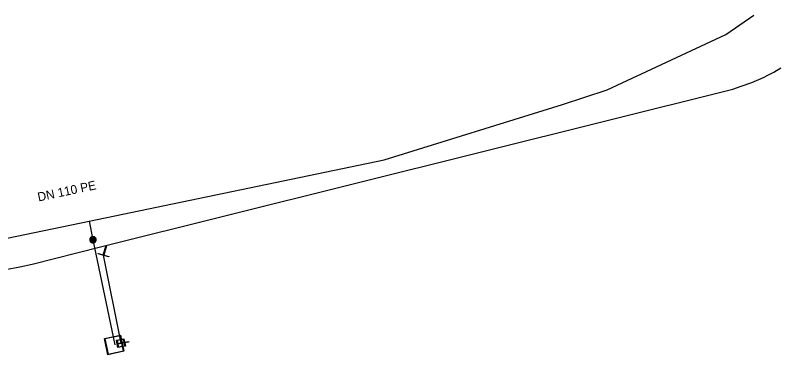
# Model space of a CAD drawing. Extents: x -818065 to -817466, y -1067968 to -1067520.
# Drawn here: x -817526.5 to -817466.3, y -1067819.3 to -1067792.5 of the extents above; entities that cross this region are included whole.
import ezdxf

# ---------------------------------------------------------------- set-up
doc = ezdxf.new("R2010")
doc.units = 0
doc.layers.add('Default', color=7, linetype='Continuous')
doc.layers.add('Level 0', color=7, linetype='Continuous')

msp = doc.modelspace()

# ---------------------------------------------------------------- linework, layer by layer
at = {"layer": 'Default'}
for points in [[(-817519.34, -1067810.682), (-817519.548, -1067811.408), (-817519.14, -1067811.525), (-817519.148, -1067811.554), (-817519.992, -1067811.312), (-817519.984, -1067811.282), (-817519.578, -1067811.4), (-817519.366, -1067810.663), (-817519.346, -1067810.658), (-817519.34, -1067810.682)], [(-817517.952, -1067818.98), (-817519.223, -1067819.251), (-817519.494, -1067817.979), (-817518.222, -1067817.709), (-817517.952, -1067818.98)], [(-817518.253, -1067817.757), (-817519.446, -1067818.01), (-817519.192, -1067819.202), (-817518, -1067818.949), (-817518.253, -1067817.757)], [(-817517.899, -1067818.263), (-817517.605, -1067818.205), (-817517.596, -1067818.254), (-817517.89, -1067818.311), (-817517.838, -1067818.581), (-817518.427, -1067818.696), (-817518.541, -1067818.107), (-817517.952, -1067817.992), (-817517.899, -1067818.263)], [(-817517.948, -1067818.272), (-817517.991, -1067818.05), (-817518.483, -1067818.146), (-817518.44, -1067818.368), (-817517.948, -1067818.272)], [(-817517.938, -1067818.32), (-817518.431, -1067818.416), (-817518.388, -1067818.638), (-817517.895, -1067818.542), (-817517.938, -1067818.32)]]:
    msp.add_lwpolyline(points, dxfattribs=at)
for points in [[(-817520.395, -1067809.954), (-817520.332, -1067809.954), (-817520.272, -1067809.986), (-817520.212, -1067810.018), (-817520.179, -1067810.079), (-817520.145, -1067810.139), (-817520.145, -1067810.204), (-817520.145, -1067810.269), (-817520.178, -1067810.329), (-817520.211, -1067810.388), (-817520.27, -1067810.421), (-817520.33, -1067810.454), (-817520.395, -1067810.454), (-817520.46, -1067810.454), (-817520.519, -1067810.421), (-817520.579, -1067810.388), (-817520.612, -1067810.329), (-817520.645, -1067810.269), (-817520.645, -1067810.204), (-817520.645, -1067810.139), (-817520.611, -1067810.079), (-817520.578, -1067810.018), (-817520.518, -1067809.986), (-817520.458, -1067809.954), (-817520.395, -1067809.954)], [(-817520.395, -1067809.977), (-817520.452, -1067809.977), (-817520.506, -1067810.007), (-817520.561, -1067810.036), (-817520.591, -1067810.09), (-817520.621, -1067810.145), (-817520.621, -1067810.204), (-817520.621, -1067810.263), (-817520.592, -1067810.317), (-817520.562, -1067810.371), (-817520.508, -1067810.401), (-817520.454, -1067810.431), (-817520.395, -1067810.431), (-817520.336, -1067810.431), (-817520.282, -1067810.401), (-817520.228, -1067810.371), (-817520.198, -1067810.317), (-817520.168, -1067810.263), (-817520.168, -1067810.204), (-817520.168, -1067810.145), (-817520.199, -1067810.09), (-817520.23, -1067810.036), (-817520.284, -1067810.007), (-817520.338, -1067809.977), (-817520.395, -1067809.977)], [(-817520.395, -1067809.995), (-817520.342, -1067809.995), (-817520.292, -1067810.022), (-817520.242, -1067810.049), (-817520.214, -1067810.099), (-817520.185, -1067810.149), (-817520.185, -1067810.204), (-817520.185, -1067810.259), (-817520.213, -1067810.309), (-817520.24, -1067810.358), (-817520.29, -1067810.386), (-817520.34, -1067810.414), (-817520.395, -1067810.414), (-817520.449, -1067810.414), (-817520.499, -1067810.386), (-817520.549, -1067810.358), (-817520.577, -1067810.309), (-817520.604, -1067810.259), (-817520.604, -1067810.204), (-817520.604, -1067810.149), (-817520.576, -1067810.099), (-817520.548, -1067810.049), (-817520.498, -1067810.022), (-817520.448, -1067809.995), (-817520.395, -1067809.995)], [(-817520.395, -1067810.017), (-817520.473, -1067810.017), (-817520.528, -1067810.071), (-817520.582, -1067810.126), (-817520.582, -1067810.204), (-817520.582, -1067810.282), (-817520.527, -1067810.337), (-817520.472, -1067810.392), (-817520.395, -1067810.392), (-817520.317, -1067810.392), (-817520.262, -1067810.337), (-817520.207, -1067810.282), (-817520.207, -1067810.204), (-817520.207, -1067810.126), (-817520.262, -1067810.071), (-817520.316, -1067810.017), (-817520.395, -1067810.017)], [(-817520.395, -1067810.039), (-817520.327, -1067810.039), (-817520.279, -1067810.087), (-817520.231, -1067810.135), (-817520.231, -1067810.204), (-817520.231, -1067810.272), (-817520.279, -1067810.32), (-817520.327, -1067810.368), (-817520.395, -1067810.368), (-817520.464, -1067810.368), (-817520.511, -1067810.32), (-817520.559, -1067810.272), (-817520.559, -1067810.204), (-817520.559, -1067810.135), (-817520.511, -1067810.087), (-817520.464, -1067810.039), (-817520.395, -1067810.039)], [(-817520.395, -1067810.059), (-817520.455, -1067810.059), (-817520.497, -1067810.102), (-817520.54, -1067810.144), (-817520.54, -1067810.204), (-817520.54, -1067810.263), (-817520.497, -1067810.306), (-817520.455, -1067810.348), (-817520.395, -1067810.348), (-817520.335, -1067810.348), (-817520.293, -1067810.306), (-817520.251, -1067810.263), (-817520.251, -1067810.204), (-817520.251, -1067810.144), (-817520.293, -1067810.102), (-817520.335, -1067810.059), (-817520.395, -1067810.059)], [(-817520.395, -1067810.079), (-817520.343, -1067810.079), (-817520.306, -1067810.116), (-817520.27, -1067810.152), (-817520.27, -1067810.204), (-817520.27, -1067810.256), (-817520.306, -1067810.293), (-817520.343, -1067810.329), (-817520.395, -1067810.329), (-817520.447, -1067810.329), (-817520.483, -1067810.293), (-817520.52, -1067810.256), (-817520.52, -1067810.204), (-817520.52, -1067810.152), (-817520.483, -1067810.116), (-817520.447, -1067810.079), (-817520.395, -1067810.079)], [(-817520.395, -1067810.102), (-817520.437, -1067810.102), (-817520.467, -1067810.132), (-817520.497, -1067810.162), (-817520.497, -1067810.204), (-817520.497, -1067810.246), (-817520.467, -1067810.276), (-817520.437, -1067810.305), (-817520.395, -1067810.305), (-817520.353, -1067810.305), (-817520.323, -1067810.276), (-817520.293, -1067810.246), (-817520.293, -1067810.204), (-817520.293, -1067810.162), (-817520.323, -1067810.132), (-817520.353, -1067810.102), (-817520.395, -1067810.102)], [(-817520.395, -1067810.12), (-817520.36, -1067810.12), (-817520.335, -1067810.144), (-817520.311, -1067810.169), (-817520.311, -1067810.204), (-817520.311, -1067810.239), (-817520.335, -1067810.263), (-817520.36, -1067810.288), (-817520.395, -1067810.288), (-817520.43, -1067810.288), (-817520.455, -1067810.263), (-817520.479, -1067810.239), (-817520.479, -1067810.204), (-817520.479, -1067810.169), (-817520.455, -1067810.144), (-817520.43, -1067810.12), (-817520.395, -1067810.12)], [(-817520.395, -1067810.142), (-817520.421, -1067810.142), (-817520.439, -1067810.16), (-817520.457, -1067810.178), (-817520.457, -1067810.204), (-817520.457, -1067810.23), (-817520.439, -1067810.248), (-817520.421, -1067810.267), (-817520.395, -1067810.267), (-817520.369, -1067810.267), (-817520.351, -1067810.248), (-817520.332, -1067810.23), (-817520.332, -1067810.204), (-817520.332, -1067810.178), (-817520.35, -1067810.16), (-817520.369, -1067810.142), (-817520.395, -1067810.142)], [(-817520.395, -1067810.165), (-817520.378, -1067810.165), (-817520.367, -1067810.176), (-817520.356, -1067810.187), (-817520.356, -1067810.204), (-817520.356, -1067810.22), (-817520.367, -1067810.232), (-817520.378, -1067810.243), (-817520.395, -1067810.243), (-817520.411, -1067810.243), (-817520.423, -1067810.232), (-817520.434, -1067810.22), (-817520.434, -1067810.204), (-817520.434, -1067810.187), (-817520.423, -1067810.176), (-817520.411, -1067810.165), (-817520.395, -1067810.165)], [(-817520.395, -1067810.181), (-817520.405, -1067810.181), (-817520.412, -1067810.187), (-817520.418, -1067810.194), (-817520.418, -1067810.204), (-817520.418, -1067810.214), (-817520.412, -1067810.221), (-817520.405, -1067810.227), (-817520.395, -1067810.227), (-817520.385, -1067810.227), (-817520.378, -1067810.221), (-817520.372, -1067810.214), (-817520.372, -1067810.204), (-817520.372, -1067810.194), (-817520.378, -1067810.187), (-817520.385, -1067810.181), (-817520.395, -1067810.181)]]:
    msp.add_open_spline(points, degree=3, dxfattribs=at)
at = {"layer": 'Level 0'}
for p, q in [((-817470.586, -1067794.06), (-817468.399, -1067792.541)), ((-817479.931, -1067798.395), (-817470.586, -1067794.06)), ((-817466.827, -1067797.009), (-817466.275, -1067796.681)), ((-817467.993, -1067797.597), (-817467.588, -1067797.404)), ((-817467.588, -1067797.404), (-817467.339, -1067797.285)), ((-817467.339, -1067797.285), (-817466.827, -1067797.009)), ((-817469.381, -1067798.126), (-817468.553, -1067797.832)), ((-817468.553, -1067797.832), (-817467.993, -1067797.597)), ((-817519.791, -1067810.768), (-817470.048, -1067798.341)), ((-817483.452, -1067799.56), (-817479.931, -1067798.395)), ((-817470.048, -1067798.341), (-817469.381, -1067798.126)), ((-817497.466, -1067803.914), (-817483.452, -1067799.56)), ((-817520.7, -1067808.735), (-817497.466, -1067803.914)), ((-817528.8, -1067810.416), (-817520.7, -1067808.735)), ((-817520.7, -1067808.735), (-817520.395, -1067810.204)), ((-817520.395, -1067810.204), (-817518.68, -1067818.466)), ((-817519.573, -1067811.418), (-817519.35, -1067810.658)), ((-817525.188, -1067812.116), (-817519.791, -1067810.768)), ((-817518.18, -1067818.34), (-817519.573, -1067811.418)), ((-817527.281, -1067812.55), (-817526.142, -1067812.333)), ((-817526.142, -1067812.333), (-817525.188, -1067812.116))]:
    msp.add_line(p, q, dxfattribs=at)

# ---------------------------------------------------------------- texts
msp.add_text('DN 110 PE', height=0.7, rotation=12, dxfattribs=at).set_placement((-817524.671, -1067807.199))

doc.saveas('drawing.dxf')
